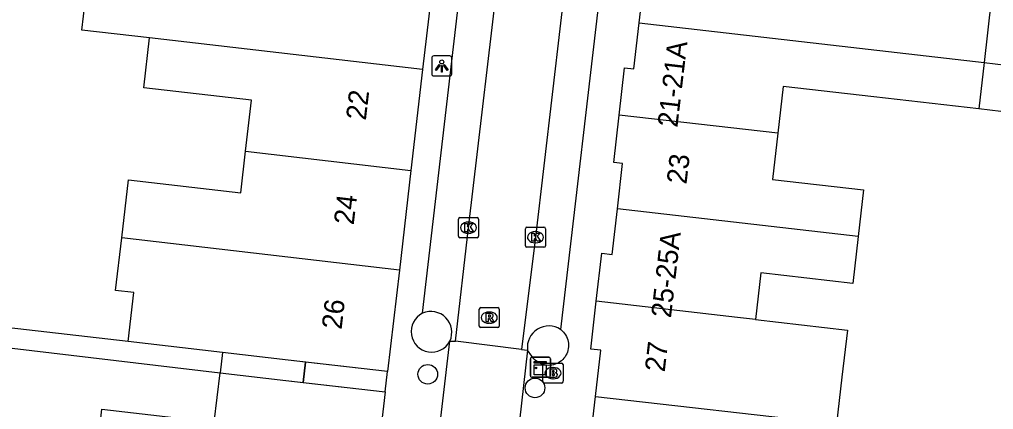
# Model space of a CAD drawing. Extents: x 161696 to 162377, y 380761 to 381673.
# Drawn here: x 162193.16 to 162241.77, y 381053.06 to 381072.52 of the extents above; entities that cross this region are included whole.
import ezdxf

# ---------------------------------------------------------------- set-up
doc = ezdxf.new("R2010")
doc.units = 0
for name, color, linetype in [('IMGEO_Boom', 7, 'Continuous'), ('IMGEO_Brandkraan', 7, 'Continuous'), ('IMGEO_Kast', 7, 'Continuous'), ('IMGEO_Kolk', 7, 'Continuous'), ('IMGEO_Lichtpunt', 7, 'Continuous'), ('IMGEO_Pand', 7, 'Continuous'), ('IMGEO_Pand_nummerreeks', 7, 'Continuous'), ('IMGEO_Pand_overbouw', 7, 'Continuous'), ('IMGEO_Parkeervlak_open', 7, 'Continuous'), ('IMGEO_Rijbaan_lokaal_open', 7, 'Continuous'), ('IMGEO_Rioolput', 7, 'Continuous'), ('IMGEO_Voetpad_open', 7, 'Continuous')]:
    doc.layers.add(name, color=color, linetype=linetype)

msp = doc.modelspace()

# ---------------------------------------------------------------- linework, layer by layer
at = {"layer": 'IMGEO_Boom'}
for centre in [(162213.534, 381054.817), (162218.885, 381054.138)]:
    msp.add_circle(centre, 0.489, dxfattribs=at)
at = {"layer": 'IMGEO_Brandkraan'}
for p, q in [((162219.359, 381055.374), (162220.211, 381055.374)), ((162219.284, 381054.448), (162219.284, 381055.3)), ((162219.772, 381055.154), (162219.797, 381055.154)), ((162220.285, 381055.3), (162220.285, 381054.448)), ((162220.211, 381054.374), (162219.359, 381054.374)), ((162219.795, 381054.594), (162219.77, 381054.594))]:
    msp.add_line(p, q, dxfattribs=at)
for points in [[(162219.359, 381055.374), (162220.211, 381055.374)], [(162219.284, 381054.448), (162219.284, 381055.3)], [(162219.632, 381055.074), (162219.632, 381054.674), (162219.845, 381054.674)], [(162219.863, 381055.074), (162219.632, 381055.074)], [(162219.811, 381054.993), (162219.757, 381054.993), (162219.757, 381054.917)], [(162219.757, 381054.917), (162219.81, 381054.917)], [(162220.285, 381055.3), (162220.285, 381054.448)], [(162220.211, 381054.374), (162219.359, 381054.374)], [(162219.819, 381054.841), (162219.757, 381054.841), (162219.757, 381054.76)], [(162219.757, 381054.76), (162219.819, 381054.76)]]:
    msp.add_lwpolyline(points, dxfattribs=at)
for centre, radius, start, end in [((162219.361, 381055.298), 0.0765, 91.552, 178.448), ((162219.361, 381055.298), 0.0765, 91.552, 178.448), ((162220.209, 381055.298), 0.0765, 1.552, 88.448), ((162220.209, 381055.298), 0.0765, 1.552, 88.448), ((162219.812, 381054.955), 0.0379, 267.8285, 90.9355), ((162219.867, 381054.929), 0.145, 59.4692, 91.5367), ((162219.892, 381054.976), 0.0922, 285.5137, 58.1501), ((162219.897, 381054.784), 0.105, 301.3115, 78.989), ((162219.361, 381054.45), 0.0765, 181.552, 268.448), ((162219.361, 381054.45), 0.0765, 181.552, 268.448), ((162219.82, 381054.8), 0.0404, 269.8759, 90.5077), ((162219.851, 381054.925), 0.251, 268.6676, 293.5347), ((162220.209, 381054.45), 0.0765, 271.552, 358.448), ((162220.209, 381054.45), 0.0765, 271.552, 358.448)]:
    msp.add_arc(centre, radius, start, end, dxfattribs=at)
for centre, major_axis, ratio, start_param, end_param in [((162219.771, 381054.874), (-0.387, 0.002), 0.722429, 4.712389, 7.853982), ((162219.796, 381054.874), (-0.39, 0.002), 0.717154, 1.570796, 4.712389)]:
    msp.add_ellipse(centre, major_axis=major_axis, ratio=ratio, start_param=start_param, end_param=end_param, dxfattribs=at)
at = {"layer": 'IMGEO_Kast'}
for p, q in [((162218.654, 381054.741), (162218.654, 381055.582)), ((162218.654, 381055.582), (162218.654, 381054.741)), ((162218.729, 381055.666), (162219.57, 381055.666)), ((162219.57, 381055.666), (162218.729, 381055.666)), ((162219.654, 381055.591), (162219.654, 381054.75)), ((162219.654, 381054.75), (162219.654, 381055.591)), ((162219.579, 381054.666), (162218.738, 381054.666)), ((162218.738, 381054.666), (162219.579, 381054.666))]:
    msp.add_line(p, q, dxfattribs=at)
for points in [[(162218.849, 381055.456), (162219.449, 381055.456), (162219.449, 381055.371), (162218.849, 381055.371), (162218.849, 381055.456)], [(162218.849, 381055.281), (162219.449, 381055.281), (162219.449, 381054.792), (162218.849, 381054.792), (162218.849, 381055.281)]]:
    msp.add_lwpolyline(points, dxfattribs=at)
msp.add_circle((162218.933, 381055.13), 0.0377, dxfattribs=at)
for centre, start, end in [((162218.732, 381055.588), 92.4484, 184.2845), ((162218.732, 381055.588), 92.4484, 184.2845), ((162219.576, 381055.588), 2.4484, 94.2845), ((162219.576, 381055.588), 2.4484, 94.2845), ((162218.732, 381054.744), 182.4484, 274.2845), ((162218.732, 381054.744), 182.4484, 274.2845), ((162219.576, 381054.744), 272.4484, 4.2845), ((162219.576, 381054.744), 272.4484, 4.2845)]:
    msp.add_arc(centre, 0.0779, start, end, dxfattribs=at)
at = {"layer": 'IMGEO_Kolk'}
for p, q in [((162215.141, 381062.631), (162215.993, 381062.631)), ((162215.066, 381061.705), (162215.066, 381062.557)), ((162215.554, 381062.411), (162215.579, 381062.411)), ((162216.067, 381062.557), (162216.067, 381061.705)), ((162218.482, 381062.154), (162219.334, 381062.154)), ((162215.577, 381061.851), (162215.552, 381061.851)), ((162218.407, 381061.228), (162218.407, 381062.08)), ((162218.895, 381061.934), (162218.92, 381061.934)), ((162219.408, 381062.08), (162219.408, 381061.228)), ((162215.993, 381061.631), (162215.141, 381061.631)), ((162218.918, 381061.374), (162218.893, 381061.374)), ((162219.334, 381061.154), (162218.482, 381061.154))]:
    msp.add_line(p, q, dxfattribs=at)
for points in [[(162215.141, 381062.631), (162215.993, 381062.631)], [(162215.066, 381061.705), (162215.066, 381062.557)], [(162215.387, 381062.331), (162215.51, 381062.331), (162215.51, 381062.18), (162215.64, 381062.331), (162215.804, 381062.331), (162215.658, 381062.18), (162215.811, 381061.931), (162215.659, 381061.931), (162215.574, 381062.095), (162215.51, 381062.028), (162215.51, 381061.931), (162215.387, 381061.931), (162215.387, 381062.331)], [(162216.067, 381062.557), (162216.067, 381061.705)], [(162218.482, 381062.154), (162219.334, 381062.154)], [(162218.407, 381061.228), (162218.407, 381062.08)], [(162218.728, 381061.854), (162218.851, 381061.854), (162218.851, 381061.703), (162218.981, 381061.854), (162219.145, 381061.854), (162218.999, 381061.703), (162219.152, 381061.454), (162219, 381061.454), (162218.915, 381061.618), (162218.851, 381061.551), (162218.851, 381061.454), (162218.728, 381061.454), (162218.728, 381061.854)], [(162219.408, 381062.08), (162219.408, 381061.228)], [(162215.993, 381061.631), (162215.141, 381061.631)], [(162219.334, 381061.154), (162218.482, 381061.154)]]:
    msp.add_lwpolyline(points, dxfattribs=at)
for centre, start, end in [((162215.143, 381062.555), 91.552, 178.448), ((162215.143, 381062.555), 91.552, 178.448), ((162215.991, 381062.555), 1.552, 88.448), ((162215.991, 381062.555), 1.552, 88.448), ((162218.484, 381062.078), 91.552, 178.448), ((162218.484, 381062.078), 91.552, 178.448), ((162219.332, 381062.078), 1.552, 88.448), ((162219.332, 381062.078), 1.552, 88.448), ((162215.143, 381061.707), 181.552, 268.448), ((162215.143, 381061.707), 181.552, 268.448), ((162215.991, 381061.707), 271.552, 358.448), ((162215.991, 381061.707), 271.552, 358.448), ((162218.484, 381061.23), 181.552, 268.448), ((162218.484, 381061.23), 181.552, 268.448), ((162219.332, 381061.23), 271.552, 358.448), ((162219.332, 381061.23), 271.552, 358.448)]:
    msp.add_arc(centre, 0.0765, start, end, dxfattribs=at)
for centre, major_axis, ratio, start_param, end_param in [((162215.553, 381062.131), (-0.387, 0.002), 0.722429, 4.712389, 7.853982), ((162215.578, 381062.131), (-0.39, 0.002), 0.717154, 1.570796, 4.712389), ((162218.894, 381061.654), (-0.387, 0.002), 0.722429, 4.712389, 7.853982), ((162218.919, 381061.654), (-0.39, 0.002), 0.717154, 1.570796, 4.712389)]:
    msp.add_ellipse(centre, major_axis=major_axis, ratio=ratio, start_param=start_param, end_param=end_param, dxfattribs=at)
at = {"layer": 'IMGEO_Lichtpunt'}
for p, q in [((162213.737, 381070.602), (162213.737, 381069.795)), ((162213.737, 381070.602), (162213.737, 381069.795)), ((162214.639, 381070.697), (162213.831, 381070.697)), ((162214.639, 381070.697), (162213.831, 381070.697)), ((162214.733, 381069.795), (162214.733, 381070.602)), ((162214.733, 381069.795), (162214.733, 381070.602)), ((162213.831, 381069.701), (162214.639, 381069.701)), ((162213.831, 381069.701), (162214.639, 381069.701))]:
    msp.add_line(p, q, dxfattribs=at)
for points in [[(162214.111, 381070.266), (162214.15, 381070.238), (162213.962, 381069.976), (162213.924, 381070.003), (162214.111, 381070.266)], [(162214.213, 381070.218), (162214.26, 381070.218), (162214.26, 381069.896), (162214.213, 381069.896), (162214.213, 381070.218)], [(162214.323, 381070.238), (162214.361, 381070.265), (162214.548, 381070.003), (162214.509, 381069.975), (162214.323, 381070.238)]]:
    msp.add_lwpolyline(points, dxfattribs=at)
msp.add_circle((162214.236, 381070.4), 0.0994, dxfattribs=at)
for centre, start, end in [((162213.831, 381070.602), 90, 180), ((162213.831, 381070.602), 90, 180), ((162214.639, 381070.602), 0, 90), ((162214.639, 381070.602), 0, 90), ((162213.831, 381069.795), 180, 270), ((162213.831, 381069.795), 180, 270), ((162214.639, 381069.795), 270, 0), ((162214.639, 381069.795), 270, 360)]:
    msp.add_arc(centre, 0.0946, start, end, dxfattribs=at)
at = {"layer": 'IMGEO_Pand'}
for points in [[(162224.082, 381072.35), (162224.344, 381074.642), (162223.874, 381074.696), (162224.148, 381077.092)], [(162199.653, 381071.598), (162196.275, 381071.99), (162196.6, 381074.793), (162199.978, 381074.401), (162202.249, 381074.137), (162202.512, 381076.4)], [(162232.084, 381076.182), (162231.815, 381073.834), (162236.327, 381073.318), (162236.411, 381074.092), (162241.65, 381073.494), (162241.294, 381070.377)], [(162213.865, 381075.086), (162213.278, 381070.021)], [(162223.083, 381067.75), (162223.353, 381070.112), (162223.82, 381070.058), (162224.082, 381072.35)], [(162224.082, 381072.35), (162241.294, 381070.377)], [(162204.445, 381065.945), (162204.74, 381068.489), (162199.364, 381069.112), (162199.653, 381071.598)], [(162213.278, 381070.021), (162199.653, 381071.598)], [(162213.278, 381070.021), (162212.694, 381064.99)], [(162241.294, 381070.377), (162242.949, 381070.178), (162242.685, 381067.866), (162241.029, 381068.055)], [(162241.294, 381070.377), (162241.029, 381068.055)], [(162241.029, 381068.055), (162235.793, 381068.653), (162231.275, 381069.169), (162231.009, 381066.844)], [(162222.995, 381063.065), (162223.255, 381065.337), (162222.813, 381065.388), (162223.083, 381067.75)], [(162231.009, 381066.844), (162223.083, 381067.75)], [(162231.009, 381066.844), (162230.745, 381064.54), (162235.279, 381064.022), (162235.012, 381061.689)], [(162198.264, 381061.622), (162198.601, 381064.525), (162204.205, 381063.875), (162204.445, 381065.945)], [(162204.445, 381065.945), (162212.694, 381064.99)], [(162212.694, 381064.99), (162212.117, 381060.019)], [(162221.945, 381058.462), (162222.219, 381060.856), (162222.736, 381060.797), (162222.995, 381063.065)], [(162235.012, 381061.689), (162222.995, 381063.065)], [(162235.012, 381061.689), (162234.745, 381059.351), (162230.148, 381059.877), (162229.882, 381057.55)], [(162198.579, 381056.448), (162198.862, 381058.895), (162197.96, 381059), (162198.264, 381061.622)], [(162212.117, 381060.019), (162198.264, 381061.622)], [(162212.117, 381060.019), (162211.529, 381054.948)], [(162221.908, 381053.712), (162222.172, 381056.015), (162221.671, 381056.072), (162221.945, 381058.462)], [(162229.882, 381057.55), (162228.99, 381057.652), (162221.945, 381058.462)], [(162229.882, 381057.55), (162234.472, 381057.023), (162234.204, 381054.677), (162233.937, 381052.341)], [(162211.529, 381054.948), (162206.563, 381055.524), (162203.289, 381055.903), (162198.579, 381056.448)], [(162196.933, 381050.121), (162197.276, 381053.072), (162202.884, 381052.421), (162203.171, 381054.889)], [(162203.171, 381054.889), (162206.446, 381054.509), (162211.412, 381053.934)], [(162211.412, 381053.934), (162210.784, 381048.518)], [(162220.864, 381049.133), (162221.131, 381051.471), (162221.645, 381051.412), (162221.908, 381053.712)], [(162221.908, 381053.712), (162233.937, 381052.341)]]:
    msp.add_lwpolyline(points, dxfattribs=at)
at = {"layer": 'IMGEO_Pand_overbouw'}
for points in [[(162203.289, 381055.903), (162203.171, 381054.889), (162206.446, 381054.509), (162207.32, 381054.408), (162207.437, 381055.423), (162206.563, 381055.524)], [(162207.437, 381055.423), (162207.32, 381054.408), (162211.412, 381053.934), (162211.529, 381054.948)]]:
    msp.add_lwpolyline(points, close=True, dxfattribs=at)
at = {"layer": 'IMGEO_Parkeervlak_open'}
for centre, radius, start, end in [((162213.696, 381056.909), 1.038, 335.3799, 113.7434), ((162219.579, 381056.152), 1.075, 57.1353, 186.813)]:
    msp.add_arc(centre, radius, start, end, dxfattribs=at)
at = {"layer": 'IMGEO_Rijbaan_lokaal_open'}
for points in [[(162214.924, 381056.471), (162215.568, 381062.131), (162217.21, 381076.083), (162218.628, 381088.239), (162219.396, 381094.73)], [(162222.682, 381094.384), (162222.002, 381088.091), (162220.579, 381075.909), (162218.907, 381061.654), (162218.219, 381056.054)], [(162213.306, 381045.133), (162214.64, 381056.476)], [(162214.64, 381056.476), (162214.924, 381056.471)], [(162218.219, 381056.054), (162214.924, 381056.471)], [(162218.512, 381056.025), (162217.228, 381044.718)], [(162218.219, 381056.054), (162218.512, 381056.025)]]:
    msp.add_lwpolyline(points, dxfattribs=at)
at = {"layer": 'IMGEO_Rioolput'}
for p, q in [((162216.102, 381057.218), (162216.102, 381058.07)), ((162216.177, 381058.144), (162217.029, 381058.144)), ((162216.59, 381057.924), (162216.615, 381057.924)), ((162217.103, 381058.07), (162217.103, 381057.218)), ((162216.613, 381057.364), (162216.588, 381057.364)), ((162217.029, 381057.144), (162216.177, 381057.144))]:
    msp.add_line(p, q, dxfattribs=at)
for points in [[(162216.102, 381057.218), (162216.102, 381058.07)], [(162216.177, 381058.144), (162217.029, 381058.144)], [(162216.691, 381057.842), (162216.439, 381057.844), (162216.439, 381057.444)], [(162216.617, 381057.763), (162216.563, 381057.763), (162216.563, 381057.682)], [(162217.103, 381058.07), (162217.103, 381057.218)], [(162216.439, 381057.444), (162216.563, 381057.444), (162216.563, 381057.606), (162216.574, 381057.606)], [(162216.563, 381057.682), (162216.615, 381057.682)], [(162216.621, 381057.577), (162216.692, 381057.444), (162216.832, 381057.444), (162216.767, 381057.57)], [(162217.029, 381057.144), (162216.177, 381057.144)]]:
    msp.add_lwpolyline(points, dxfattribs=at)
for centre, radius, start, end in [((162216.179, 381058.068), 0.0765, 91.552, 178.448), ((162216.179, 381058.068), 0.0765, 91.552, 178.448), ((162216.623, 381057.667), 0.0964, 77.0061, 93.1865), ((162216.637, 381057.724), 0.0378, 276.6634, 79.6772), ((162216.69, 381057.732), 0.109, 350.3612, 89.416), ((162217.027, 381058.068), 0.0765, 1.552, 88.448), ((162217.027, 381058.068), 0.0765, 1.552, 88.448), ((162216.573, 381057.553), 0.0533, 26.0293, 88.6989), ((162216.599, 381057.871), 0.19, 274.7715, 282.9687), ((162216.688, 381057.732), 0.112, 277.5842, 350.9817), ((162216.672, 381057.517), 0.108, 29.5134, 73.7905), ((162216.179, 381057.22), 0.0765, 181.552, 268.448), ((162216.179, 381057.22), 0.0765, 181.552, 268.448), ((162217.027, 381057.22), 0.0765, 271.552, 358.448), ((162217.027, 381057.22), 0.0765, 271.552, 358.448)]:
    msp.add_arc(centre, radius, start, end, dxfattribs=at)
for centre, major_axis, ratio, start_param, end_param in [((162216.589, 381057.644), (-0.387, 0.002), 0.722429, 4.712389, 7.853982), ((162216.614, 381057.644), (-0.39, 0.002), 0.717154, 1.570796, 4.712389)]:
    msp.add_ellipse(centre, major_axis=major_axis, ratio=ratio, start_param=start_param, end_param=end_param, dxfattribs=at)
at = {"layer": 'IMGEO_Voetpad_open'}
for points in [[(162213.278, 381057.859), (162217.494, 381094.168)], [(162224.378, 381093.251), (162220.162, 381057.055)], [(162198.579, 381056.448), (162184.803, 381058.031), (162186.119, 381069.511)], [(162220.162, 381057.055), (162220.174, 381057.046), (162220.242, 381056.988), (162220.305, 381056.925), (162220.361, 381056.856), (162220.412, 381056.782), (162220.455, 381056.705), (162220.492, 381056.623), (162220.521, 381056.539), (162220.542, 381056.453), (162220.555, 381056.365), (162220.561, 381056.276), (162220.559, 381056.187), (162220.548, 381056.098), (162220.53, 381056.011), (162220.504, 381055.926), (162220.471, 381055.843), (162220.43, 381055.764), (162220.383, 381055.689), (162220.328, 381055.618), (162220.268, 381055.552), (162220.202, 381055.492), (162220.132, 381055.438), (162220.056, 381055.391), (162219.977, 381055.351), (162219.894, 381055.318), (162219.809, 381055.292), (162219.721, 381055.274), (162219.633, 381055.264), (162219.544, 381055.262), (162219.455, 381055.268), (162219.367, 381055.281), (162219.281, 381055.303), (162219.197, 381055.332), (162219.115, 381055.369), (162219.038, 381055.413), (162218.964, 381055.463), (162218.896, 381055.52), (162218.833, 381055.583), (162218.775, 381055.651), (162218.724, 381055.724), (162218.512, 381056.025)], [(162187.312, 381056.762), (162203.171, 381054.889)], [(162211.412, 381053.934), (162211.529, 381054.948)]]:
    msp.add_lwpolyline(points, dxfattribs=at)
msp.add_arc((162213.729, 381056.941), 1.023, 116.1479, 332.9754, dxfattribs=at)

# ---------------------------------------------------------------- texts
at = {"layer": 'IMGEO_Pand_nummerreeks'}
for s, rotation, p in [('21-21A', 83.2794, (162225.989, 381067.105)), ('22', 83.3826, (162210.444, 381067.46)), ('23', 83.381, (162226.443, 381064.273)), ('24', 83.3826, (162209.838, 381062.245)), ('25-25A', 83.3825, (162225.668, 381057.601)), ('26', 83.3826, (162209.233, 381057.026)), ('27', 83.3825, (162225.356, 381054.903))]:
    msp.add_text(s, height=1, rotation=rotation, dxfattribs=at).set_placement(p)

doc.saveas('drawing.dxf')
